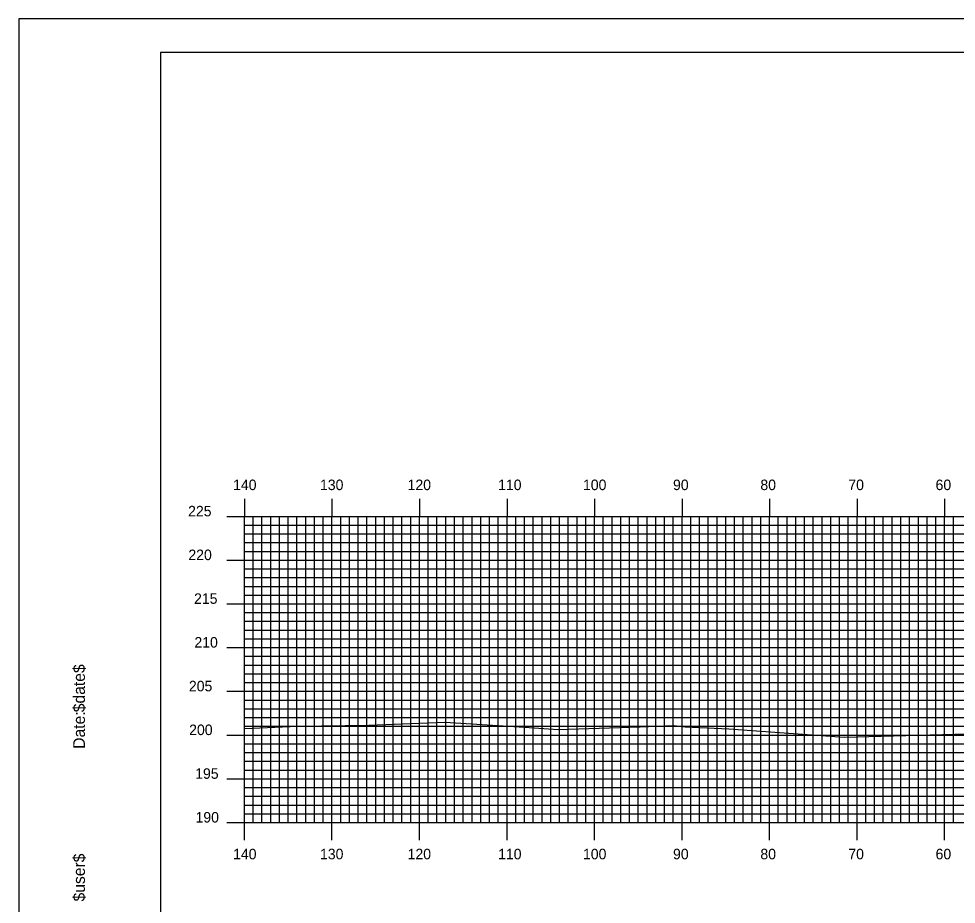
# Model space of a CAD drawing. Extents: x 1811767 to 1812110, y 442591 to 442811.
# Drawn here: x 1811767.1 to 1811874.3, y 442709.3 to 442810.5 of the extents above; entities that cross this region are included whole.
import ezdxf

# ---------------------------------------------------------------- set-up
doc = ezdxf.new("R2010")
doc.units = 0
for name, color, linetype in [('BORDER', 7, 'Continuous'), ('H_V ANNOTATION', 7, 'Continuous'), ('MAJOR', 7, 'Continuous'), ('MINOR', 7, 'Continuous'), ('PLOT BOUNDARY', 7, 'Continuous'), ('S_Roadway_Centerline', 7, 'Continuous')]:
    doc.layers.add(name, color=color, linetype=linetype)

msp = doc.modelspace()

# ---------------------------------------------------------------- linework, layer by layer
at = {"layer": 'BORDER'}
msp.add_lwpolyline([(1811783.32, 442596.67), (1812103.32, 442596.67), (1812103.32, 442806.67), (1811783.32, 442806.67)], close=True, dxfattribs=at)
at = {"layer": 'MAJOR'}
for p, q in [((1811792.92, 442755.67), (1811792.92, 442753.67)), ((1811802.92, 442755.67), (1811802.92, 442753.67)), ((1811812.92, 442755.67), (1811812.92, 442753.67)), ((1811822.92, 442755.67), (1811822.92, 442753.67)), ((1811832.92, 442755.67), (1811832.92, 442753.67)), ((1811842.92, 442755.67), (1811842.92, 442753.67)), ((1811852.92, 442755.67), (1811852.92, 442753.67)), ((1811862.92, 442755.67), (1811862.92, 442753.67)), ((1811872.92, 442755.67), (1811872.92, 442753.67)), ((1811790.91, 442753.67), (1811792.92, 442753.67)), ((1811792.92, 442753.67), (1812072.92, 442753.67)), ((1811792.92, 442718.67), (1811792.92, 442753.67)), ((1811792.92, 442718.67), (1811792.92, 442753.67)), ((1811792.92, 442753.67), (1812072.92, 442753.67)), ((1811802.92, 442718.67), (1811802.92, 442753.67)), ((1811812.92, 442718.67), (1811812.92, 442753.67)), ((1811822.92, 442718.67), (1811822.92, 442753.67)), ((1811832.92, 442718.67), (1811832.92, 442753.67)), ((1811842.92, 442718.67), (1811842.92, 442753.67)), ((1811852.92, 442718.67), (1811852.92, 442753.67)), ((1811862.92, 442718.67), (1811862.92, 442753.67)), ((1811872.92, 442718.67), (1811872.92, 442753.67)), ((1811790.91, 442748.67), (1811792.92, 442748.67)), ((1811792.92, 442748.67), (1812072.92, 442748.67)), ((1811790.91, 442743.67), (1811792.92, 442743.67)), ((1811792.92, 442743.67), (1812072.92, 442743.67)), ((1811790.91, 442738.67), (1811792.92, 442738.67)), ((1811792.92, 442738.67), (1812072.92, 442738.67)), ((1811790.91, 442733.67), (1811792.92, 442733.67)), ((1811792.92, 442733.67), (1812072.92, 442733.67)), ((1811790.91, 442728.67), (1811792.92, 442728.67)), ((1811792.92, 442728.67), (1812072.92, 442728.67)), ((1811790.91, 442723.67), (1811792.92, 442723.67)), ((1811792.92, 442723.67), (1812072.92, 442723.67)), ((1811790.91, 442718.67), (1811792.92, 442718.67)), ((1811792.92, 442718.67), (1812072.92, 442718.67)), ((1811792.92, 442718.67), (1812072.92, 442718.67)), ((1811792.92, 442716.66), (1811792.92, 442718.67)), ((1811802.92, 442716.66), (1811802.92, 442718.67)), ((1811812.92, 442716.66), (1811812.92, 442718.67)), ((1811822.92, 442716.66), (1811822.92, 442718.67)), ((1811832.92, 442716.66), (1811832.92, 442718.67)), ((1811842.92, 442716.66), (1811842.92, 442718.67)), ((1811852.92, 442716.66), (1811852.92, 442718.67)), ((1811862.92, 442716.66), (1811862.92, 442718.67)), ((1811872.92, 442716.66), (1811872.92, 442718.67))]:
    msp.add_line(p, q, dxfattribs=at)
at = {"layer": 'MINOR'}
for p, q in [((1811793.92, 442718.67), (1811793.92, 442753.67)), ((1811794.92, 442718.67), (1811794.92, 442753.67)), ((1811795.92, 442718.67), (1811795.92, 442753.67)), ((1811796.92, 442718.67), (1811796.92, 442753.67)), ((1811797.92, 442718.67), (1811797.92, 442753.67)), ((1811798.92, 442718.67), (1811798.92, 442753.67)), ((1811799.92, 442718.67), (1811799.92, 442753.67)), ((1811800.92, 442718.67), (1811800.92, 442753.67)), ((1811801.92, 442718.67), (1811801.92, 442753.67)), ((1811803.92, 442718.67), (1811803.92, 442753.67)), ((1811804.92, 442718.67), (1811804.92, 442753.67)), ((1811805.92, 442718.67), (1811805.92, 442753.67)), ((1811806.92, 442718.67), (1811806.92, 442753.67)), ((1811807.92, 442718.67), (1811807.92, 442753.67)), ((1811808.92, 442718.67), (1811808.92, 442753.67)), ((1811809.92, 442718.67), (1811809.92, 442753.67)), ((1811810.92, 442718.67), (1811810.92, 442753.67)), ((1811811.92, 442718.67), (1811811.92, 442753.67)), ((1811813.92, 442718.67), (1811813.92, 442753.67)), ((1811814.92, 442718.67), (1811814.92, 442753.67)), ((1811815.92, 442718.67), (1811815.92, 442753.67)), ((1811816.92, 442718.67), (1811816.92, 442753.67)), ((1811817.92, 442718.67), (1811817.92, 442753.67)), ((1811818.92, 442718.67), (1811818.92, 442753.67)), ((1811819.92, 442718.67), (1811819.92, 442753.67)), ((1811820.92, 442718.67), (1811820.92, 442753.67)), ((1811821.92, 442718.67), (1811821.92, 442753.67)), ((1811823.92, 442718.67), (1811823.92, 442753.67)), ((1811824.92, 442718.67), (1811824.92, 442753.67)), ((1811825.92, 442718.67), (1811825.92, 442753.67)), ((1811826.92, 442718.67), (1811826.92, 442753.67)), ((1811827.92, 442718.67), (1811827.92, 442753.67)), ((1811828.92, 442718.67), (1811828.92, 442753.67)), ((1811829.92, 442718.67), (1811829.92, 442753.67)), ((1811830.92, 442718.67), (1811830.92, 442753.67)), ((1811831.92, 442718.67), (1811831.92, 442753.67)), ((1811833.92, 442718.67), (1811833.92, 442753.67)), ((1811834.92, 442718.67), (1811834.92, 442753.67)), ((1811835.92, 442718.67), (1811835.92, 442753.67)), ((1811836.92, 442718.67), (1811836.92, 442753.67)), ((1811837.92, 442718.67), (1811837.92, 442753.67)), ((1811838.92, 442718.67), (1811838.92, 442753.67)), ((1811839.92, 442718.67), (1811839.92, 442753.67)), ((1811840.92, 442718.67), (1811840.92, 442753.67)), ((1811841.92, 442718.67), (1811841.92, 442753.67)), ((1811843.92, 442718.67), (1811843.92, 442753.67)), ((1811844.92, 442718.67), (1811844.92, 442753.67)), ((1811845.92, 442718.67), (1811845.92, 442753.67)), ((1811846.92, 442718.67), (1811846.92, 442753.67)), ((1811847.92, 442718.67), (1811847.92, 442753.67)), ((1811848.92, 442718.67), (1811848.92, 442753.67)), ((1811849.92, 442718.67), (1811849.92, 442753.67)), ((1811850.92, 442718.67), (1811850.92, 442753.67)), ((1811851.92, 442718.67), (1811851.92, 442753.67)), ((1811853.92, 442718.67), (1811853.92, 442753.67)), ((1811854.92, 442718.67), (1811854.92, 442753.67)), ((1811855.92, 442718.67), (1811855.92, 442753.67)), ((1811856.92, 442718.67), (1811856.92, 442753.67)), ((1811857.92, 442718.67), (1811857.92, 442753.67)), ((1811858.92, 442718.67), (1811858.92, 442753.67)), ((1811859.92, 442718.67), (1811859.92, 442753.67)), ((1811860.92, 442718.67), (1811860.92, 442753.67)), ((1811861.92, 442718.67), (1811861.92, 442753.67)), ((1811863.92, 442718.67), (1811863.92, 442753.67)), ((1811864.92, 442718.67), (1811864.92, 442753.67)), ((1811865.92, 442718.67), (1811865.92, 442753.67)), ((1811866.92, 442718.67), (1811866.92, 442753.67)), ((1811867.92, 442718.67), (1811867.92, 442753.67)), ((1811868.92, 442718.67), (1811868.92, 442753.67)), ((1811869.92, 442718.67), (1811869.92, 442753.67)), ((1811870.92, 442718.67), (1811870.92, 442753.67)), ((1811871.92, 442718.67), (1811871.92, 442753.67)), ((1811873.92, 442718.67), (1811873.92, 442753.67)), ((1811792.92, 442752.67), (1812072.92, 442752.67)), ((1811792.92, 442752.67), (1811794.92, 442752.67)), ((1811792.92, 442751.67), (1812072.92, 442751.67)), ((1811792.92, 442751.67), (1811794.92, 442751.67)), ((1811792.92, 442750.67), (1812072.92, 442750.67)), ((1811792.92, 442750.67), (1811794.92, 442750.67)), ((1811792.92, 442749.67), (1812072.92, 442749.67)), ((1811792.92, 442749.67), (1811794.92, 442749.67)), ((1811792.92, 442747.67), (1812072.92, 442747.67)), ((1811792.92, 442747.67), (1811794.92, 442747.67)), ((1811792.92, 442746.67), (1812072.92, 442746.67)), ((1811792.92, 442746.67), (1811794.92, 442746.67)), ((1811792.92, 442745.67), (1812072.92, 442745.67)), ((1811792.92, 442745.67), (1811794.92, 442745.67)), ((1811792.92, 442744.67), (1812072.92, 442744.67)), ((1811792.92, 442744.67), (1811794.92, 442744.67)), ((1811792.92, 442742.67), (1812072.92, 442742.67)), ((1811792.92, 442742.67), (1811794.92, 442742.67)), ((1811792.92, 442741.67), (1812072.92, 442741.67)), ((1811792.92, 442741.67), (1811794.92, 442741.67)), ((1811792.92, 442740.67), (1812072.92, 442740.67)), ((1811792.92, 442740.67), (1811794.92, 442740.67)), ((1811792.92, 442739.67), (1812072.92, 442739.67)), ((1811792.92, 442739.67), (1811794.92, 442739.67)), ((1811792.92, 442737.67), (1812072.92, 442737.67)), ((1811792.92, 442737.67), (1811794.92, 442737.67)), ((1811792.92, 442736.67), (1812072.92, 442736.67)), ((1811792.92, 442736.67), (1811794.92, 442736.67)), ((1811792.92, 442735.67), (1812072.92, 442735.67)), ((1811792.92, 442735.67), (1811794.92, 442735.67)), ((1811792.92, 442734.67), (1812072.92, 442734.67)), ((1811792.92, 442734.67), (1811794.92, 442734.67)), ((1811792.92, 442732.67), (1812072.92, 442732.67)), ((1811792.92, 442732.67), (1811794.92, 442732.67)), ((1811792.92, 442731.67), (1812072.92, 442731.67)), ((1811792.92, 442731.67), (1811794.92, 442731.67)), ((1811792.92, 442730.67), (1812072.92, 442730.67)), ((1811792.92, 442730.67), (1811794.92, 442730.67)), ((1811792.92, 442729.67), (1812072.92, 442729.67)), ((1811792.92, 442729.67), (1811794.92, 442729.67)), ((1811792.92, 442727.67), (1812072.92, 442727.67)), ((1811792.92, 442727.67), (1811794.92, 442727.67)), ((1811792.92, 442726.67), (1812072.92, 442726.67)), ((1811792.92, 442726.67), (1811794.92, 442726.67)), ((1811792.92, 442725.67), (1812072.92, 442725.67)), ((1811792.92, 442725.67), (1811794.92, 442725.67)), ((1811792.92, 442724.67), (1812072.92, 442724.67)), ((1811792.92, 442724.67), (1811794.92, 442724.67)), ((1811792.92, 442722.67), (1812072.92, 442722.67)), ((1811792.92, 442722.67), (1811794.92, 442722.67)), ((1811792.92, 442721.67), (1812072.92, 442721.67)), ((1811792.92, 442721.67), (1811794.92, 442721.67)), ((1811792.92, 442720.67), (1812072.92, 442720.67)), ((1811792.92, 442720.67), (1811794.92, 442720.67)), ((1811792.92, 442719.67), (1812072.92, 442719.67)), ((1811792.92, 442719.67), (1811794.92, 442719.67))]:
    msp.add_line(p, q, dxfattribs=at)
at = {"layer": 'PLOT BOUNDARY'}
msp.add_lwpolyline([(1811767.13, 442590.55), (1812107.13, 442590.55), (1812107.13, 442810.55), (1811767.13, 442810.55)], close=True, dxfattribs=at)
at = {"layer": 'S_Roadway_Centerline'}
msp.add_lwpolyline([(1811792.92, 442729.42), (1811799, 442729.68), (1811807.12, 442729.8), (1811815.83, 442730.15), (1811824.9, 442729.58), (1811828.78, 442729.29), (1811838.13, 442729.63), (1811842, 442729.76), (1811843.28, 442729.62), (1811848.25, 442729.4), (1811861.44, 442728.43), (1811876.92, 442728.86)], dxfattribs=at)

# ---------------------------------------------------------------- texts
at = {"layer": 'BORDER'}
for s, p in [('$date$', (1811774.69, 442731.28)), ('Date:', (1811774.69, 442727.1)), ('$user$', (1811774.69, 442709.65))]:
    msp.add_text(s, height=1.339, rotation=90, dxfattribs=at).set_placement(p)
at = {"layer": 'H_V ANNOTATION'}
for s, p in [('140', (1811791.62, 442756.67)), ('130', (1811801.55, 442756.67)), ('120', (1811811.56, 442756.67)), ('110', (1811821.9, 442756.67)), ('100', (1811831.6, 442756.67)), ('90', (1811841.89, 442756.67)), ('80', (1811851.87, 442756.67)), ('70', (1811861.92, 442756.67)), ('60', (1811871.89, 442756.67)), ('225', (1811786.48, 442753.67)), ('220', (1811786.51, 442748.67)), ('215', (1811787.16, 442743.67)), ('210', (1811787.2, 442738.67)), ('205', (1811786.57, 442733.67)), ('200', (1811786.6, 442728.67)), ('195', (1811787.29, 442723.67)), ('190', (1811787.33, 442718.67)), ('140', (1811791.62, 442714.47)), ('130', (1811801.55, 442714.47)), ('120', (1811811.56, 442714.47)), ('110', (1811821.9, 442714.47)), ('100', (1811831.6, 442714.47)), ('90', (1811841.89, 442714.47)), ('80', (1811851.87, 442714.47)), ('70', (1811861.92, 442714.47)), ('60', (1811871.89, 442714.47))]:
    msp.add_text(s, height=1.2, dxfattribs=at).set_placement(p)
at = {"layer": 'MAJOR'}
msp.add_text('-', height=0.012, dxfattribs=at).set_placement((1811792.91, 442718.67))

doc.saveas('drawing.dxf')
